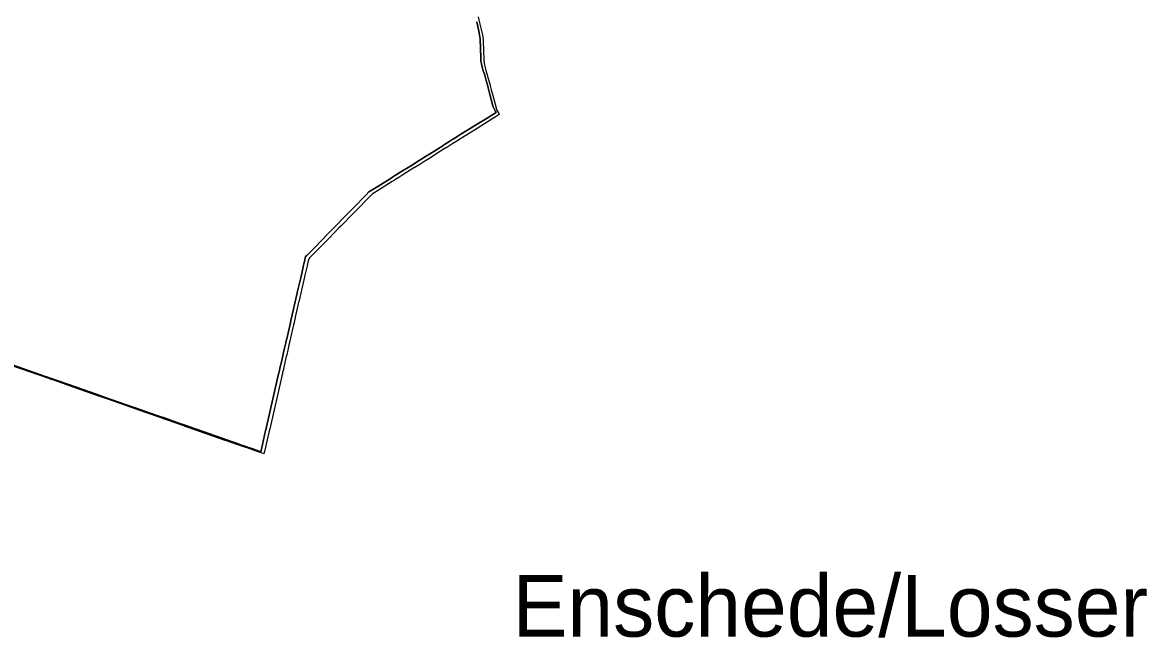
# Model space of a CAD drawing. Extents: x 113371 to 291721, y 393993 to 520143.
# Drawn here: x 250494 to 259635, y 470735 to 475732 of the extents above; entities that cross this region are included whole.
import ezdxf

# ---------------------------------------------------------------- set-up
doc = ezdxf.new("R2010")
doc.units = 0
for name, color, linetype in [('Boudingbox', 7, 'Continuous'), ('Default', 7, 'Continuous'), ('plaatsnamen', 7, 'Continuous')]:
    doc.layers.add(name, color=color, linetype=linetype)

msp = doc.modelspace()

# ---------------------------------------------------------------- linework, layer by layer
at = {"layer": 'Boudingbox'}
msp.add_lwpolyline([(254199.874, 475778.443), (254213.616, 475718.956), (254233.977, 475630.819), (254239.553, 475594.573), (254241.235, 475583.639), (254241.751, 475580.286), (254247.037, 475427.608), (254248.283, 475398.643), (254253.257, 475377.03), (254264.289, 475330.229), (254272.614, 475306.33), (254276.711, 475294.582), (254279.157, 475285.862), (254294.223, 475232.158), (254300.808, 475206.609), (254306.675, 475183.843), (254318.372, 475139.483), (254345.254, 475037.493), (254347.151, 475030.489), (254348.471, 475025.613), (254349.063, 475023.428), (254366.879, 474990.986), (254371.16, 474983.167), (254337.495, 474962.017), (254336.63, 474961.473), (254336.466, 474961.37), (254329.264, 474956.845), (254327.519, 474955.764), (254314.765, 474947.829), (254311.803, 474945.99), (254191.467, 474871.281), (254064.243, 474792.298), (254055.624, 474786.865), (254055.281, 474786.649), (254026.911, 474768.768), (253995.206, 474748.783), (253994.765, 474748.505), (253944.669, 474716.931), (253943.736, 474716.343), (253939.546, 474713.702), (253937.294, 474712.283), (253893.712, 474684.905), (253798.093, 474624.447), (253767.112, 474604.833), (253725.452, 474579.071), (253679.495, 474550.532), (253679.032, 474550.245), (253677.782, 474549.469), (253669.901, 474544.608), (253669.44, 474544.323), (253596.733, 474499.478), (253554.269, 474472.905), (253529.012, 474456.969), (253511.995, 474446.338), (253500.813, 474439.35), (253381.319, 474364.696), (253337.437, 474337.951), (253314.159, 474312.818), (253207.914, 474204.677), (253172.972, 474169.214), (253153.09, 474148.912), (253149.072, 474144.81), (253149.057, 474144.794), (253131.555, 474126.922), (253128.176, 474123.471), (253123.144, 474118.333), (253083.279, 474077.763), (253068.195, 474062.385), (253033.16, 474026.737), (252979.627, 473971.46), (252976.122, 473967.903), (252973.459, 473965.199), (252874.488, 473864.728), (252858.775, 473848.748), (252839.259, 473829.042), (252831.885, 473821.618), (252821.798, 473811.338), (252815.607, 473784.328), (252806.017, 473743.219), (252793.498, 473689.171), (252782.399, 473640.465), (252754.757, 473520.867), (252752.614, 473511.515), (252743.102, 473470.012), (252742.875, 473469.02), (252713.075, 473338.731), (252712.492, 473336.182), (252711.903, 473333.612), (252703.046, 473294.943), (252702.942, 473294.491), (252698.258, 473274.043), (252666.038, 473133.397), (252665.909, 473132.834), (252665.365, 473130.459), (252661.041, 473111.583), (252660.948, 473111.175), (252651.274, 473068.947), (252651.196, 473068.605), (252642.789, 473031.906), (252642.763, 473031.793), (252639.836, 473019.016), (252639.784, 473018.789), (252636.778, 473005.67), (252619.777, 472931.453), (252619.366, 472929.659), (252612.951, 472901.658), (252612.558, 472899.942), (252610.129, 472889.34), (252609.614, 472887.091), (252607.579, 472878.208), (252603.595, 472860.814), (252603.117, 472858.729), (252504.493, 472429.776), (252500.642, 472413.184), (252500.253, 472411.334), (252498.171, 472402.278), (252497.533, 472399.502), (252462.447, 472246.901), (252457.803, 472226.694), (252452.519, 472228.527), (252452.09, 472228.676), (252402.111, 472246.058), (252312.467, 472277.236), (252310.376, 472277.963), (252261.015, 472295.13), (252257.214, 472296.452), (252256.617, 472296.66), (252256.436, 472296.723), (252246.034, 472300.364), (252237.083, 472303.498), (252145.266, 472335.64), (252142.96, 472336.448), (251834.375, 472444.477), (251818.233, 472450.128), (251807.404, 472453.977), (251674.02, 472500.512), (251666.316, 472503.207), (251664.905, 472503.701), (251655.938, 472506.841), (251614.888, 472521.199), (251606.107, 472524.266), (251431.177, 472585.489), (251427.828, 472586.662), (251187.672, 472670.6), (251114.949, 472696.057), (250960.707, 472750.051), (250740.989, 472826.969), (250740.915, 472826.995), (250725.89, 472832.259), (250715.563, 472835.864), (250393.806, 472948.632)], dxfattribs=at)
at = {"layer": 'Default'}
for points in [[(254001.205625, 474786.5225), (254029.575625, 474804.4025), (254029.915625, 474804.6225), (254038.535625, 474810.0525), (254165.755625, 474889.0425), (254286.095625, 474963.7425), (254289.055625, 474965.5825), (254301.805625, 474973.5225), (254303.555625, 474974.6025), (254310.755625, 474979.1325), (254310.915625, 474979.2325), (254311.785625, 474979.7725), (254345.445625, 475000.9225), (254341.165625, 475008.7425), (254323.355625, 475041.1825), (254322.765625, 475043.3725), (254321.445625, 475048.2425), (254319.545625, 475055.2525), (254292.665625, 475157.2425), (254280.965625, 475201.6025), (254275.095625, 475224.3625), (254268.515625, 475249.9125), (254253.445625, 475303.6225), (254251.005625, 475312.3425), (254246.905625, 475324.0825), (254238.575625, 475347.9825), (254227.545625, 475394.7925), (254222.575625, 475416.4025), (254221.325625, 475445.3625), (254216.045625, 475598.0425), (254215.525625, 475601.3925), (254213.845625, 475612.3325), (254208.265625, 475648.5725), (254187.905625, 475736.7125)], [(254187.905625, 475736.7125), (254208.265625, 475648.5725), (254213.845625, 475612.3325), (254215.525625, 475601.3925), (254216.045625, 475598.0425), (254221.325625, 475445.3625), (254222.575625, 475416.4025), (254227.545625, 475394.7925), (254238.575625, 475347.9825), (254246.905625, 475324.0825), (254251.005625, 475312.3425), (254253.445625, 475303.6225), (254268.515625, 475249.9125), (254275.095625, 475224.3625), (254280.965625, 475201.6025), (254292.665625, 475157.2425), (254319.545625, 475055.2525)], [(254319.545625, 475055.2525), (254321.445625, 475048.2425), (254322.765625, 475043.3725), (254323.355625, 475041.1825), (254341.165625, 475008.7425), (254345.445625, 475000.9225), (254311.785625, 474979.7725), (254310.915625, 474979.2325), (254310.755625, 474979.1325), (254303.555625, 474974.6025), (254301.805625, 474973.5225), (254289.055625, 474965.5825), (254286.095625, 474963.7425), (254165.755625, 474889.0425), (254038.535625, 474810.0525), (254029.915625, 474804.6225), (254029.575625, 474804.4025), (254001.205625, 474786.5225), (253994.935625, 474782.5725), (253969.495625, 474766.5425), (253969.055625, 474766.2625), (253918.955625, 474734.6925), (253918.025625, 474734.1025), (253913.835625, 474731.4625), (253911.585625, 474730.0425), (253868.005625, 474702.6625), (253802.855625, 474661.4725), (253772.385625, 474642.2025), (253741.405625, 474622.5925), (253699.745625, 474596.8325), (253653.785625, 474568.2925), (253653.325625, 474568.0025), (253652.075625, 474567.2225), (253644.195625, 474562.3625), (253643.735625, 474562.0825), (253571.025625, 474517.2325), (253528.555625, 474490.6625), (253503.305625, 474474.7225)], [(252953.915625, 473989.2225), (253007.445625, 474044.4925), (253042.485625, 474080.1425), (253057.565625, 474095.5225), (253097.435625, 474136.0925), (253102.465625, 474141.2325), (253105.845625, 474144.6825), (253123.345625, 474162.5525), (253123.365625, 474162.5625), (253127.375625, 474166.6725), (253147.265625, 474186.9725), (253182.205625, 474222.4325), (253288.445625, 474330.5725), (253311.725625, 474355.7125), (253355.605625, 474382.4525), (253475.105625, 474457.1125), (253486.285625, 474464.0925), (253503.305625, 474474.7225), (253528.555625, 474490.6625), (253571.025625, 474517.2325), (253643.735625, 474562.0825), (253644.195625, 474562.3625), (253652.075625, 474567.2225), (253653.325625, 474568.0025), (253653.785625, 474568.2925), (253699.745625, 474596.8325), (253741.405625, 474622.5925), (253772.385625, 474642.2025), (253802.855625, 474661.4725), (253868.005625, 474702.6625), (253911.585625, 474730.0425), (253913.835625, 474731.4625), (253918.025625, 474734.1025), (253918.955625, 474734.6925), (253969.055625, 474766.2625), (253969.495625, 474766.5425), (253994.935625, 474782.5725), (254001.205625, 474786.5225)], [(253503.305625, 474474.7225), (253486.285625, 474464.0925), (253475.105625, 474457.1125), (253355.605625, 474382.4525), (253311.725625, 474355.7125), (253288.445625, 474330.5725), (253182.205625, 474222.4325), (253147.265625, 474186.9725), (253127.375625, 474166.6725), (253123.365625, 474162.5625), (253123.345625, 474162.5525), (253105.845625, 474144.6825), (253102.465625, 474141.2325), (253097.435625, 474136.0925), (253057.565625, 474095.5225), (253042.485625, 474080.1425), (253007.445625, 474044.4925), (252953.915625, 473989.2225), (252950.415625, 473985.6625), (252947.745625, 473982.9525), (252848.775625, 473882.4825), (252833.065625, 473866.5025), (252813.545625, 473846.8025), (252806.175625, 473839.3725), (252796.085625, 473829.0925), (252789.895625, 473802.0825), (252782.055625, 473768.4525), (252780.465625, 473761.6425), (252780.305625, 473760.9725), (252767.785625, 473706.9325), (252756.685625, 473658.2225), (252729.045625, 473538.6225), (252726.905625, 473529.2725), (252717.395625, 473487.7725), (252717.165625, 473486.7725), (252687.365625, 473356.4925), (252686.785625, 473353.9425), (252686.195625, 473351.3725)], [(252594.065625, 472949.2125), (252611.065625, 473023.4325), (252614.075625, 473036.5425), (252614.125625, 473036.7725), (252617.055625, 473049.5525), (252617.075625, 473049.6625), (252625.485625, 473086.3625), (252625.565625, 473086.7025), (252635.235625, 473128.9325), (252635.335625, 473129.3425), (252639.655625, 473148.2125), (252640.195625, 473150.5925), (252640.325625, 473151.1525), (252672.545625, 473291.8025), (252677.235625, 473312.2525), (252677.335625, 473312.7025), (252684.145625, 473342.4225), (252686.195625, 473351.3725), (252686.785625, 473353.9425), (252687.365625, 473356.4925), (252717.165625, 473486.7725), (252717.395625, 473487.7725), (252726.905625, 473529.2725), (252729.045625, 473538.6225), (252756.685625, 473658.2225), (252767.785625, 473706.9325), (252780.305625, 473760.9725), (252780.465625, 473761.6425), (252782.055625, 473768.4525), (252789.895625, 473802.0825), (252796.085625, 473829.0925), (252806.175625, 473839.3725), (252813.545625, 473846.8025), (252833.065625, 473866.5025), (252848.775625, 473882.4825), (252947.745625, 473982.9525), (252950.415625, 473985.6625), (252953.915625, 473989.2225)], [(252686.195625, 473351.3725), (252684.145625, 473342.4225), (252677.335625, 473312.7025), (252677.235625, 473312.2525), (252672.545625, 473291.8025), (252640.325625, 473151.1525), (252640.195625, 473150.5925), (252639.655625, 473148.2125), (252635.335625, 473129.3425), (252635.235625, 473128.9325), (252625.565625, 473086.7025), (252625.485625, 473086.3625), (252617.075625, 473049.6625), (252617.055625, 473049.5525), (252614.125625, 473036.7725), (252614.075625, 473036.5425), (252611.065625, 473023.4325), (252594.065625, 472949.2125), (252593.655625, 472947.4125), (252587.245625, 472919.4125), (252586.845625, 472917.7025), (252584.415625, 472907.0925), (252583.905625, 472904.8525), (252581.865625, 472895.9625), (252577.885625, 472878.5725), (252577.405625, 472876.4825), (252478.785625, 472447.5325), (252474.935625, 472430.9425), (252474.545625, 472429.0925), (252472.465625, 472420.0325), (252471.825625, 472417.2625), (252436.735625, 472264.6625), (252432.095625, 472244.4525), (252426.805625, 472246.2825), (252426.375625, 472246.4325), (252376.405625, 472263.8125), (252286.755625, 472294.9925), (252284.665625, 472295.7225)], [(252284.665625, 472295.7225), (252235.305625, 472312.8825), (252231.505625, 472314.2125), (252230.905625, 472314.4125), (252230.725625, 472314.4825), (252220.325625, 472318.1225), (252211.375625, 472321.2525), (252210.225625, 472321.6525), (252119.555625, 472353.3925), (252117.255625, 472354.2025), (251808.665625, 472462.2325), (251792.525625, 472467.8825), (251781.695625, 472471.7325), (251648.305625, 472518.2725), (251640.605625, 472520.9625), (251639.195625, 472521.4625), (251630.225625, 472524.6025), (251589.175625, 472538.9525), (251580.395625, 472542.0225), (251405.465625, 472603.2425), (251402.115625, 472604.4225), (251161.965625, 472688.3625), (251089.235625, 472713.8125), (250934.995625, 472767.8125), (250715.275625, 472844.7225), (250715.205625, 472844.7525), (250700.175625, 472850.0125), (250689.855625, 472853.6225), (250368.095625, 472966.3925)], [(250368.095625, 472966.3925), (250689.855625, 472853.6225), (250700.175625, 472850.0125), (250715.205625, 472844.7525), (250715.275625, 472844.7225), (250934.995625, 472767.8125), (251089.235625, 472713.8125), (251161.965625, 472688.3625), (251402.115625, 472604.4225), (251405.465625, 472603.2425), (251580.395625, 472542.0225), (251589.175625, 472538.9525)], [(251589.175625, 472538.9525), (251630.225625, 472524.6025), (251639.195625, 472521.4625), (251640.605625, 472520.9625), (251648.305625, 472518.2725), (251781.695625, 472471.7325), (251792.525625, 472467.8825), (251808.665625, 472462.2325), (252117.255625, 472354.2025), (252119.555625, 472353.3925), (252210.225625, 472321.6525), (252211.375625, 472321.2525), (252220.325625, 472318.1225), (252230.725625, 472314.4825), (252230.905625, 472314.4125), (252231.505625, 472314.2125), (252235.305625, 472312.8825), (252284.665625, 472295.7225), (252286.755625, 472294.9925), (252376.405625, 472263.8125), (252426.375625, 472246.4325), (252426.805625, 472246.2825), (252432.095625, 472244.4525), (252436.735625, 472264.6625), (252471.825625, 472417.2625), (252472.465625, 472420.0325), (252474.545625, 472429.0925), (252474.935625, 472430.9425), (252478.785625, 472447.5325), (252577.405625, 472876.4825), (252577.885625, 472878.5725), (252581.865625, 472895.9625), (252583.905625, 472904.8525), (252584.415625, 472907.0925), (252586.845625, 472917.7025), (252587.245625, 472919.4125), (252593.655625, 472947.4125), (252594.065625, 472949.2125)]]:
    msp.add_lwpolyline(points, dxfattribs=at)

# ---------------------------------------------------------------- texts
at = {"layer": 'plaatsnamen'}
msp.add_text('Enschede/Losser', height=500, dxfattribs=at).set_placement((254479.44109, 470741.816257))

doc.saveas('drawing.dxf')
